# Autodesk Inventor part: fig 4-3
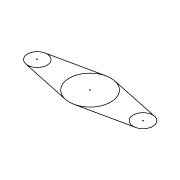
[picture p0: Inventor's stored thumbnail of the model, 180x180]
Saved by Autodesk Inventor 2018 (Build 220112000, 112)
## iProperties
Created: 2005-02
Part Number: fig 4-3
Document SubType Name: Modeling
Designer: CADCIM
Manufacturer: Standard
Standards Organization: Custom
Density: 1 g/cm^3
Material: Generic
Appearance: Default
Author: CADCIM
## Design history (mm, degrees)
sketch "Sketch1"
  geometry: L1 (-33.874, 5.844)-(-2.722, 12.469); L2 (2.595, 12.472)-(33.871, 5.852); L3 (-33.884, -5.902)-(-2.745, -12.585); L4 (2.595, -12.592)-(33.871, -5.972); A1 r 12.81 centre (-0.057, -0.06) between (-2.722, 12.469) and (2.595, 12.472); A2 r 6.006 centre (-32.624, -0.03) between (-33.874, 5.844) and (-33.884, -5.902); A3 r 6.043 centre (32.619, -0.06) between (33.871, 5.852) and (33.871, -5.972)
  constraints: 8 end point, 8 point on circle, 8 tangent, 3 centre point, 1 other
